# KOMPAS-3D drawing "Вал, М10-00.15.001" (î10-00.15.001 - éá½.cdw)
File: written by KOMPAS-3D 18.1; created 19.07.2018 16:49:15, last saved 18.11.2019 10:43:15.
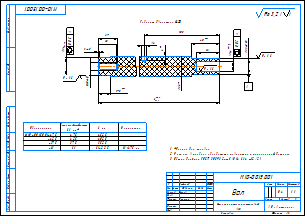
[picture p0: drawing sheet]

Sheet 1: A3, landscape

Document properties: Организация: Мирончук; Полное имя файла: D:\Magna\Магна Ins\Магна ins 10\М10-00.00.000\3Д\М10-00.15.001 - Вал.cdw; Масса: 0.395722; Параметр неуказанной шероховатости: Ra 3,2

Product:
- Part/product: Вал  | designation М10-00.15.001
    Масса: 0.395722
    Раздел спецификации: Детали
    Форматы листов документа: 2xA3
    Примечание: @100~)2xA3
    Плотность: 2000
    source file: М10-00.15.001 - Вал.cdw

Title block, sheet 1: Наименование: Вал; designation: М10-00.15.001; Материал: Стержень стеклопластиковый; Масса: 0,4; scale: 1:1; Количество листов документа: 1; organisation: АО «Астерион»; Форматы листов документа: A3; stored path: Z:\Магна\Магна Ins\Магна ins 10\М10-00.00.000\3Д\М10-00.15.001 - Вал.cdw; Разработал: Милов; Т. контр.: Лучихин

Views: Вид 1, Местный разрез 1, Спереди, Проекционный вид 2, Проекционный вид 4, Проекционный вид 6, Вид:1
Referenced files in Z:\Магна\Магна Ins\Магна ins 10\М10-00.00.000\3Д\: М10-00.15.001 - Вал.m3d, М10-00.15.001-02 - Вал.m3d, М10-00.15.001-01 - Вал.m3d
Referenced files in D:\Magna\Магна Ins\Магна ins 10\М10-00.00.000\3Д\: М10-00.15.001-01 - Вал.m3d, М10-00.15.001-02 - Вал.m3d, М10-00.15.001 - Вал.m3d
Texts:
  Ra 1,6
  Длина погружной части
  L1, мм*
  L, мм
  L1 475 мм
  Габарит двигателя 63
  Ra 3,2
  Ra 3,2 ( )
  Лифлянд
Dimensions and other numbers on the sheet: -6Н; 10; 1; 17,5; 32; 40; 105; 14; 22±0,02; 0,02; 6; 24; 0,05; 25; 27; 28; 475; 452,5; -425; -375; 425; 375; 402,5; 352,5; 0; 1:1; 0,4; 29.10.2019

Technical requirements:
  *Размер для справок.
  Размеры в скобках обработать совместно с сопрягаемой
  деталью.
  Общие допуски ГОСТ 30893.2-тК (H14, h14,  t2/2).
